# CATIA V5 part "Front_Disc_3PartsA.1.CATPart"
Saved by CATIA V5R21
Part number: Front_Disc_3PartsA.1
Property "V_Scale": "NormalScale"
Property "V_isTerminal": "true"
Property "V_ChangeHistory": "false"
Property "V_isLastVersion": "false"
Property "V_isVPLMControlled": "true"
Property "V_AuthorityControl": "false"
Property "V_ProjectApplicability": "List"
Property "V_Name": "Front_Disc_3Parts"
Property "PLM_ExternalID": "prd-R1132100306978-00000014"
Property "V_description": " "
Property "V_usage": "3DPart"
Property "V_nature": "Definition"
Property "V_sec_level": "0"
Property "owner": "lightandshadows"
Property "project": "Common Space"
Property "organization": "Company Name"
Property "revision": "A.1"
Property "originated": "10/07/2015 :: 02:19:47 "
Property "modified": "06/20/2017 :: 04:59:00 "
Property "reserved": "false"
Property "current": "IN_WORK"
Property "name": "prd-R1132100306978-00000014"
Property "locked": "false"
Property "revindex": "0"
Property "isbestsofar": "true"
Property "minorrevision": "1"
Property "majorrevision": "A"
Property "ispublished": "false"
Property "policy": "VPLM_SMB_Definition"
Bounding box of the stored display mesh (mm): x -160 to 160, y -159.96 to 159.958, z 0 to 17
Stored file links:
  E:\Desktop\AXEL\A1\Front_Disc_3PartsA.1.CATPart

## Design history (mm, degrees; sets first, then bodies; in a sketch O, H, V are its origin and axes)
Body1 "Front-Disc_1Part" (main body)
  Solid1: solid without history
  DatumCurve1 "Axe.1"
  DatumCurve2 "Axe.2"
  DatumCurve3 "Axe.3"
  Point1 "Esquisse.1": stored without definition
  Plane1: stored without definition
  DatumCurve4 "Axe.4"
  Plane2 "Plan.8": stored without definition
  Plane3 "Plan.9": stored without definition
  Plane4 "Plan.10": stored without definition
Body2 "Front-Disc_3Parts_01"
  Solid2: solid without history
Body3 "Front-Disc_3Parts_02"
  Solid3: solid without history
Body4 "Front-Disc_3Parts_03"
  Solid4: solid without history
